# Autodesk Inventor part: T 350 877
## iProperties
Company: Mayer & Müller AG Schaltgeräte
Created: 2005-12
Part Number: T 350 877
Material: 2.0060.30
Document SubType Name: Modeling
Designer: I.Baliuc
Manufacturer: Standard
Standards Organization: Custom
Description: Leitblech
Density: 8.94 g/cm^3
HalbzeugNorm: DIN 1759
Zweck: für LBK
Abmessung: 12 x 8 - 205
Author: T.Messerschmitt
Keywords: 382055
Revision Number: 350877
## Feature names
1. Extrusion2
2. Fase1 [Chamfer]
3. Bohrung1 [Hole]
